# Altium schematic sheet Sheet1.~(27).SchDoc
size A
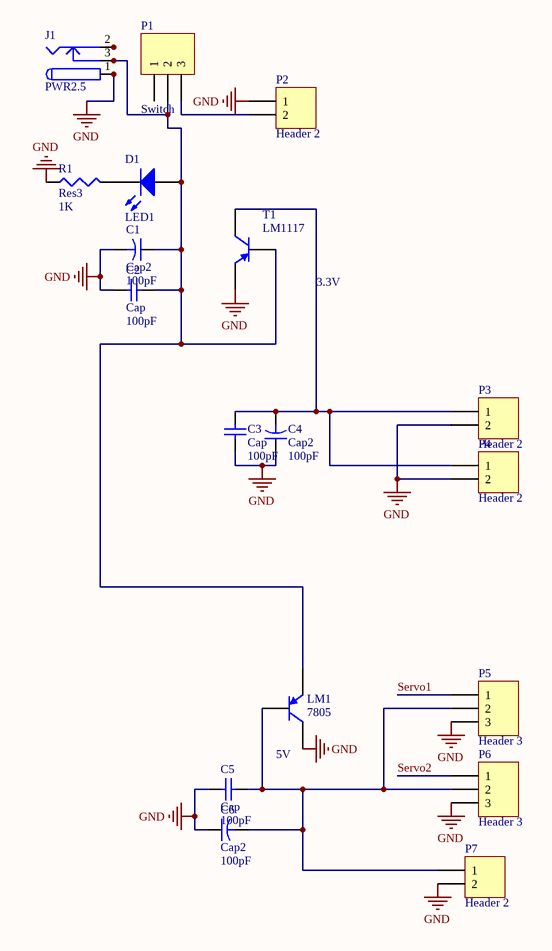
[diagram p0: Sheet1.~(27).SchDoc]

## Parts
C1  Cap2  value 100pF  [CAPR5-4X5]
C2  Cap  value 100pF  [RAD-0.2]
C3  Cap  value 100pF  [RAD-0.2]
C4  Cap2  value 100pF  [CAPR5-4X5]
C5  Cap  value 100pF  [RAD-0.2]
C6  Cap2  value 100pF  [CAPR5-4X5]
D1  LED1  [LED-1]
J1  PWR2.5  [KLD-0202]
LM1  7805  [TO-220-AB]
P1  Switch  [HDR1X3]
P2  Header 2  [HDR1X2]
P3  Header 2  [HDR1X2]
P4  Header 2  [HDR1X2]
P5  Header 3  [HDR1X3]
P6  Header 3  [HDR1X3]
P7  Header 2  [HDR1X2]
R1  Res3  value 1K  [J1-0603]
T1  LM1117  [TO-220-AB]

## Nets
GND: C1.2 C2.1 C3.2 C4.1 C5.2 C6.1 J1.1 J1.1A J1.1B LM1.2(B) P2.1 P3.2 P4.2 P5.3 P6.3 P7.2 R1.1 T1.1(E)
Servo1: P5.1
Servo2: P6.1
NetC1_1: C1.1 C2.2 D1.1(A) J1.3 J1.3A J1.3B LM1.1(E) P1.2 T1.3(C)
NetC3_1: C3.1 C4.2 P3.1 P4.1 T1.2(B)
NetC5_1: C5.1 C6.2 LM1.3(C) P5.2 P6.2 P7.1
NetD1_2: D1.2(K) R1.2
NetJ1_2: J1.2 J1.2A J1.2B
NetP1_3: P1.3 P2.2

Not connected (* = marked no-connect by the designer): P1 1

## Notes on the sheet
- 3.3V
- (near LM1) 5V

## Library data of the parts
C1 C4 C6 = Cap2: Capacitor
C2 C3 C5 = Cap: Capacitor
D1 = LED1: Typical RED GaAs LED
J1 = PWR2.5: Low Voltage Power Supply Connector
LM1 T1 = 2N3906: PNP General Purpose Amplifier
P1 P5 P6 = Header 3: Header, 3-Pin
P2-P4 P7 = Header 2: Header, 2-Pin
R1 = Res3: Resistor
